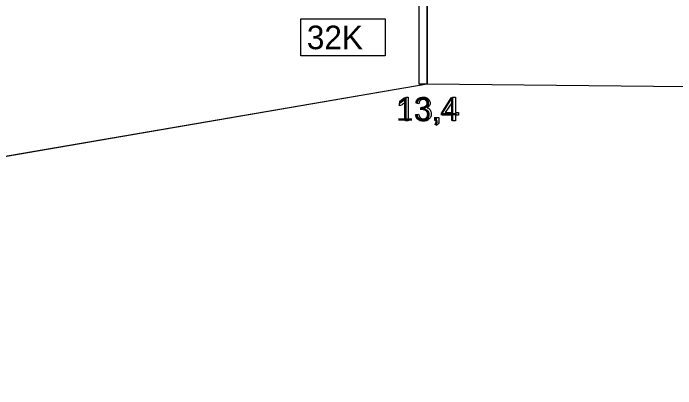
# Model space of a CAD drawing. Extents: x 532503 to 539665, y 6557663 to 6561526.
# Drawn here: x 537829 to 537986.3, y 6560151 to 6560240.2 of the extents above; entities that cross this region are included whole.
import ezdxf

# ---------------------------------------------------------------- set-up
doc = ezdxf.new("R2010")
doc.units = 0
for name, color, linetype in [('GEOLPUNKT', 7, 'Continuous'), ('Kaitsevöönd', 7, 'Continuous'), ('Proovid', 7, 'Continuous'), ('Täide', 7, 'Continuous')]:
    doc.layers.add(name, color=color, linetype=linetype)

msp = doc.modelspace()

# ---------------------------------------------------------------- linework, layer by layer
at = {"layer": 'GEOLPUNKT'}
msp.add_line((537927.28, 6560491.47), (537927.28, 6560223.47), dxfattribs=at)
for points in [[(537922.33, 6560220.29), (537922.77, 6560220.29), (537922.77, 6560214.67)], [(537933.26, 6560214.67), (537933.26, 6560216.01), (537930.83, 6560216.01), (537930.83, 6560216.64), (537933.38, 6560220.27), (537933.94, 6560220.27), (537933.94, 6560216.64), (537934.7, 6560216.64), (537934.7, 6560216.01), (537933.94, 6560216.01), (537933.94, 6560214.67), (537933.26, 6560214.67)], [(537920.71, 6560218.22), (537920.71, 6560218.89)], [(537922.77, 6560214.67), (537922.08, 6560214.67), (537922.08, 6560219.05)], [(537925.29, 6560218.72), (537924.6, 6560218.84)], [(537925.89, 6560217.33), (537925.97, 6560217.93)], [(537933.26, 6560216.64), (537933.26, 6560219.17), (537931.5, 6560216.64), (537933.26, 6560216.64)], [(537924.54, 6560216.16), (537925.22, 6560216.25)], [(537929.25, 6560214.67), (537929.25, 6560215.45), (537930.03, 6560215.45), (537930.03, 6560214.67)], [(537929.4, 6560213.56), (537929.21, 6560213.85)], [(537929.64, 6560214.67), (537929.25, 6560214.67)]]:
    msp.add_lwpolyline(points, dxfattribs=at)
for points in [[(537920.71, 6560218.89), (537921.28, 6560219.16), (537921.72, 6560219.54), (537922.15, 6560219.93), (537922.33, 6560220.29)], [(537924.6, 6560218.84), (537924.73, 6560219.53), (537925.18, 6560219.91), (537925.62, 6560220.29), (537926.29, 6560220.29), (537926.75, 6560220.29), (537927.13, 6560220.1), (537927.52, 6560219.9), (537927.72, 6560219.56), (537927.93, 6560219.22), (537927.93, 6560218.84), (537927.93, 6560218.48), (537927.73, 6560218.18), (537927.54, 6560217.88), (537927.16, 6560217.71), (537927.65, 6560217.59), (537927.93, 6560217.23), (537928.2, 6560216.87), (537928.2, 6560216.33), (537928.2, 6560215.6), (537927.67, 6560215.09), (537927.13, 6560214.58), (537926.32, 6560214.58), (537925.58, 6560214.58), (537925.09, 6560215.02), (537924.6, 6560215.46), (537924.54, 6560216.16)], [(537925.97, 6560217.93), (537926.04, 6560217.92), (537926.08, 6560217.92), (537926.52, 6560217.92), (537926.87, 6560218.15), (537927.22, 6560218.38), (537927.22, 6560218.85), (537927.22, 6560219.23), (537926.96, 6560219.48), (537926.71, 6560219.73), (537926.3, 6560219.73), (537925.9, 6560219.73), (537925.64, 6560219.48), (537925.37, 6560219.22), (537925.29, 6560218.72)], [(537922.08, 6560219.05), (537921.83, 6560218.81), (537921.43, 6560218.58), (537921.03, 6560218.34), (537920.71, 6560218.22)], [(537925.22, 6560216.25), (537925.34, 6560215.66), (537925.63, 6560215.4), (537925.91, 6560215.14), (537926.32, 6560215.14), (537926.81, 6560215.14), (537927.14, 6560215.48), (537927.47, 6560215.82), (537927.47, 6560216.31), (537927.47, 6560216.79), (537927.16, 6560217.09), (537926.85, 6560217.4), (537926.38, 6560217.4), (537926.18, 6560217.4), (537925.89, 6560217.33)], [(537929.21, 6560213.85), (537929.42, 6560213.95), (537929.53, 6560214.14), (537929.63, 6560214.32), (537929.64, 6560214.67)], [(537930.03, 6560214.67), (537930.03, 6560214.24), (537929.88, 6560213.97), (537929.73, 6560213.71), (537929.4, 6560213.56)]]:
    msp.add_open_spline(points, degree=3, dxfattribs=at)
at = {"layer": 'Kaitsevöönd'}
msp.add_lwpolyline([(537081.83, 6560005.9), (537114.82, 6560006.67), (537183.93, 6560026.73), (537280.03, 6560100.21), (537353.48, 6560157.72), (537409.98, 6560181.67), (537680.4, 6560181.07), (537927.28, 6560223.47), (538157.31, 6560221.07), (538426.58, 6560200.27), (538783.9, 6560154.27), (538809.14, 6560154.38)], dxfattribs=at)
at = {"layer": 'Proovid'}
for points in [[(537927.28, 6560245.47), (537925.28, 6560245.47), (537925.28, 6560223.47), (537927.28, 6560223.47)], [(537897.28, 6560238.87), (537917.28, 6560238.87), (537917.28, 6560230.07), (537897.28, 6560230.07)]]:
    msp.add_lwpolyline(points, close=True, dxfattribs=at)
at = {"layer": 'Täide'}
msp.add_line((537680.4, 6560181.07), (537927.28, 6560223.47), dxfattribs=at)
for points in [[(537822.21, 6560205.42), (537927.28, 6560223.47), (538157.31, 6560221.07), (538426.58, 6560200.27), (538783.9, 6560154.27), (538809.14, 6560154.38)], [(537927.28, 6560223.47), (538157.31, 6560221.07), (538426.58, 6560200.27), (538783.9, 6560154.27)]]:
    msp.add_lwpolyline(points, dxfattribs=at)

# ---------------------------------------------------------------- texts
at = {"layer": 'GEOLPUNKT'}
msp.add_text('13,4', height=5.6, dxfattribs=at).set_placement((537919.86, 6560214.67))
at = {"layer": 'Proovid'}
msp.add_text('32K', height=5.6, dxfattribs=at).set_placement((537898.68, 6560231.67))

doc.saveas('drawing.dxf')
